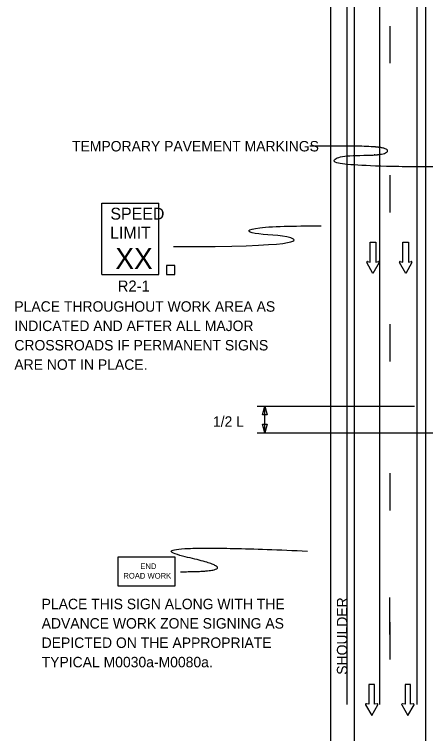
# Model space of a CAD drawing. Extents: x 16765 to 18475, y 6981 to 8262.
# Drawn here: x 16764.7 to 17041.1, y 7413.7 to 7896.5 of the extents above; entities that cross this region are included whole.
import ezdxf

# ---------------------------------------------------------------- set-up
doc = ezdxf.new("R2010")
doc.units = 0
for name, color, linetype in [('ALI_LEGAL_EX', 7, 'Continuous'), ('MT_SCRATCH_LEVEL_E', 7, 'Continuous'), ('PAVT_EDGE_EX', 7, 'Continuous'), ('TRAFFIC_SIGNS_PR', 7, 'Continuous'), ('TYPICAL_TEXT_DIMEN_PR', 7, 'Continuous')]:
    doc.layers.add(name, color=color, linetype=linetype)

msp = doc.modelspace()

# ---------------------------------------------------------------- linework, layer by layer
at = {"layer": 'ALI_LEGAL_EX'}
for points in [[(17017.08, 7888.47), (17017.08, 7863.81)], [(17017.08, 7788.47), (17017.08, 7763.47)], [(17017.08, 7688.47), (17017.08, 7663.47)], [(17017.08, 7588.47), (17017.08, 7563.47)], [(17017.08, 7488.47), (17017.08, 7463.47)]]:
    msp.add_lwpolyline(points, dxfattribs=at)
at = {"layer": 'MT_SCRATCH_LEVEL_E'}
for p, q in [((17003.82, 7730.24), (17003.82, 7743.5)), ((17003.82, 7743.5), (17007.56, 7743.5)), ((17003.82, 7730.24), (17003.82, 7743.5)), ((17003.82, 7743.5), (17007.56, 7743.5)), ((17007.56, 7743.5), (17007.56, 7730.24)), ((17007.56, 7743.5), (17007.56, 7730.24)), ((17025.85, 7730.24), (17025.85, 7743.5)), ((17025.85, 7743.5), (17029.59, 7743.5)), ((17025.85, 7730.24), (17025.85, 7743.5)), ((17025.85, 7743.5), (17029.59, 7743.5)), ((17029.59, 7743.5), (17029.59, 7730.24)), ((17029.59, 7743.5), (17029.59, 7730.24)), ((17002.04, 7730.56), (17003.82, 7730.24)), ((17002.04, 7730.56), (17003.82, 7730.24)), ((17007.56, 7730.24), (17009.33, 7730.56)), ((17007.56, 7730.24), (17009.33, 7730.56)), ((17024.07, 7730.56), (17025.85, 7730.24)), ((17024.07, 7730.56), (17025.85, 7730.24)), ((17029.59, 7730.24), (17031.37, 7730.56)), ((17029.59, 7730.24), (17031.37, 7730.56)), ((17005.67, 7722.64), (17001.56, 7729.88)), ((17005.67, 7722.64), (17001.56, 7729.88)), ((17009.81, 7729.88), (17005.67, 7722.64)), ((17009.81, 7729.88), (17005.67, 7722.64)), ((17027.7, 7722.64), (17023.59, 7729.88)), ((17027.7, 7722.64), (17023.59, 7729.88)), ((17031.85, 7729.88), (17027.7, 7722.64)), ((17031.85, 7729.88), (17027.7, 7722.64)), ((17006.75, 7446.6), (17003.01, 7446.6)), ((17003.01, 7446.6), (17003.01, 7433.34)), ((17006.75, 7446.6), (17003.01, 7446.6)), ((17003.01, 7446.6), (17003.01, 7433.34)), ((17006.75, 7433.34), (17006.75, 7446.6)), ((17006.75, 7433.34), (17006.75, 7446.6)), ((17031.01, 7446.6), (17027.26, 7446.6)), ((17027.26, 7446.6), (17027.26, 7433.34)), ((17031.01, 7446.6), (17027.26, 7446.6)), ((17027.26, 7446.6), (17027.26, 7433.34)), ((17031.01, 7433.34), (17031.01, 7446.6)), ((17031.01, 7433.34), (17031.01, 7446.6)), ((17000.75, 7432.97), (17004.9, 7425.73)), ((17000.75, 7432.97), (17004.9, 7425.73)), ((17003.01, 7433.34), (17001.23, 7433.65)), ((17003.01, 7433.34), (17001.23, 7433.65)), ((17004.9, 7425.73), (17009.01, 7432.97)), ((17004.9, 7425.73), (17009.01, 7432.97)), ((17008.53, 7433.65), (17006.75, 7433.34)), ((17008.53, 7433.65), (17006.75, 7433.34)), ((17025.01, 7432.97), (17029.15, 7425.73)), ((17025.01, 7432.97), (17029.15, 7425.73)), ((17027.26, 7433.34), (17025.49, 7433.65)), ((17027.26, 7433.34), (17025.49, 7433.65)), ((17029.15, 7425.73), (17033.27, 7432.97)), ((17029.15, 7425.73), (17033.27, 7432.97)), ((17032.78, 7433.65), (17031.01, 7433.34)), ((17032.78, 7433.65), (17031.01, 7433.34))]:
    msp.add_line(p, q, dxfattribs=at)
for centre, start, end in [((17001.96, 7730.1), 80.0362, 209.5752), ((17001.96, 7730.1), 80.0362, 209.5752), ((17009.4, 7730.1), 330.2269, 99.9638), ((17009.4, 7730.1), 330.2269, 99.9638), ((17024, 7730.1), 80.0362, 209.5752), ((17024, 7730.1), 80.0362, 209.5752), ((17031.44, 7730.1), 330.2269, 99.9638), ((17031.44, 7730.1), 330.2269, 99.9638), ((17001.16, 7433.19), 80.0362, 209.7731), ((17001.16, 7433.19), 80.0362, 209.7731), ((17008.6, 7433.19), 330.4248, 99.9638), ((17008.6, 7433.19), 330.4248, 99.9638), ((17025.42, 7433.19), 80.0362, 209.7731), ((17025.42, 7433.19), 80.0362, 209.7731), ((17032.86, 7433.19), 330.4248, 99.9638), ((17032.86, 7433.19), 330.4248, 99.9638)]:
    msp.add_arc(centre, 0.463, start, end, dxfattribs=at)
at = {"layer": 'PAVT_EDGE_EX'}
for p, q in [((16988.15, 8262.34), (16988.15, 7433.15)), ((17010.15, 8262.34), (17010.15, 7433.15)), ((17035.15, 8262.34), (17035.15, 7433.15)), ((16977.08, 8196.54), (16977.08, 7351.89)), ((16993.08, 8196.54), (16993.08, 7351.89)), ((17041.08, 8196.54), (17041.08, 7351.89))]:
    msp.add_line(p, q, dxfattribs=at)
msp.add_lwpolyline([(17017.08, 7480.11), (17017.08, 7505.11)], dxfattribs=at)
at = {"layer": 'TRAFFIC_SIGNS_PR'}
for p, q in [((16823.51, 7769.84), (16861.91, 7769.84)), ((16823.51, 7721.84), (16823.51, 7769.84)), ((16861.91, 7721.84), (16861.91, 7769.84)), ((16823.51, 7721.84), (16861.91, 7721.84))]:
    msp.add_line(p, q, dxfattribs=at)
for points in [[(16866.92, 7721.84), (16872.52, 7721.84), (16872.52, 7728.01), (16866.92, 7728.01)], [(16834.36, 7512.97), (16872.76, 7512.97), (16872.76, 7532.17), (16834.36, 7532.17)]]:
    msp.add_lwpolyline(points, close=True, dxfattribs=at)
msp.add_open_spline([(16876.36, 7522.35), (16923.59, 7522.35), (16838.57, 7541.7), (16961.67, 7536.21)], degree=2, dxfattribs=at)
at = {"layer": 'TYPICAL_TEXT_DIMEN_PR'}
for p, q in [((16927.98, 7633.46), (17033.61, 7633.46)), ((16931.41, 7627.6), (16932.98, 7633.46)), ((16932.98, 7615.49), (16932.98, 7633.46)), ((16932.98, 7633.46), (16934.55, 7627.6)), ((16932.98, 7627.6), (16931.41, 7627.6)), ((16934.55, 7627.6), (16932.98, 7627.6)), ((16932.98, 7615.49), (16931.41, 7621.36)), ((16931.41, 7621.36), (16932.98, 7621.36)), ((16932.98, 7621.36), (16934.55, 7621.36)), ((16934.55, 7621.36), (16932.98, 7615.49)), ((16927.98, 7615.49), (17057.62, 7615.49))]:
    msp.add_line(p, q, dxfattribs=at)
for points, degree in [([(17064.36, 7793.98), (16979.58, 7793.98), (16979.58, 7801.85), (17015.54, 7801.85), (17015.54, 7808.01), (16967.25, 7808.01), (16963.31, 7808.01)], 2), ([(16871.63, 7740.58), (16956.41, 7740.58), (16956.41, 7748.45), (16920.45, 7748.45), (16920.45, 7754.1), (16957.46, 7754.54), (16970.88, 7754.59)], 3)]:
    msp.add_open_spline(points, degree=degree, dxfattribs=at)

# ---------------------------------------------------------------- texts
at = {"layer": 'TRAFFIC_SIGNS_PR'}
for s, height, p in [('SPEED', 8, (16829.27, 7758.71)), ('LIMIT', 8, (16829.11, 7745.91)), ('XX', 14.031, (16832.62, 7725.6)), ('R2-1', 7.44, (16834.18, 7710.4)), ('PLACE THROUGHOUT WORK AREA AS', 7, (16764.73, 7696.9)), ('INDICATED AND AFTER ALL MAJOR', 7, (16764.73, 7683.9)), ('CROSSROADS IF PERMANENT SIGNS', 7, (16764.73, 7670.9)), ('ARE NOT IN PLACE.', 7, (16764.73, 7657.9)), ('END', 3.831, (16849.37, 7524.1)), ('ROAD WORK', 3.831, (16837.97, 7517.72)), ('PLACE THIS SIGN ALONG WITH THE', 7, (16783.08, 7497.19)), ('ADVANCE WORK ZONE SIGNING AS', 7, (16783.08, 7484.19)), ('DEPICTED ON THE APPROPRIATE', 7, (16783.08, 7471.19)), ('TYPICAL M0030a-M0080a.', 7, (16783.08, 7458.19))]:
    msp.add_text(s, height=height, dxfattribs=at).set_placement(p)
at = {"layer": 'TYPICAL_TEXT_DIMEN_PR'}
for s, p in [('TEMPORARY PAVEMENT MARKINGS', (16803.47, 7804.49)), ('1/2 L', (16898.18, 7619.68))]:
    msp.add_text(s, height=7, dxfattribs=at).set_placement(p)
msp.add_text('SHOULDER', height=7, rotation=90, dxfattribs=at).set_placement((16988.46, 7453.16))

doc.saveas('drawing.dxf')
